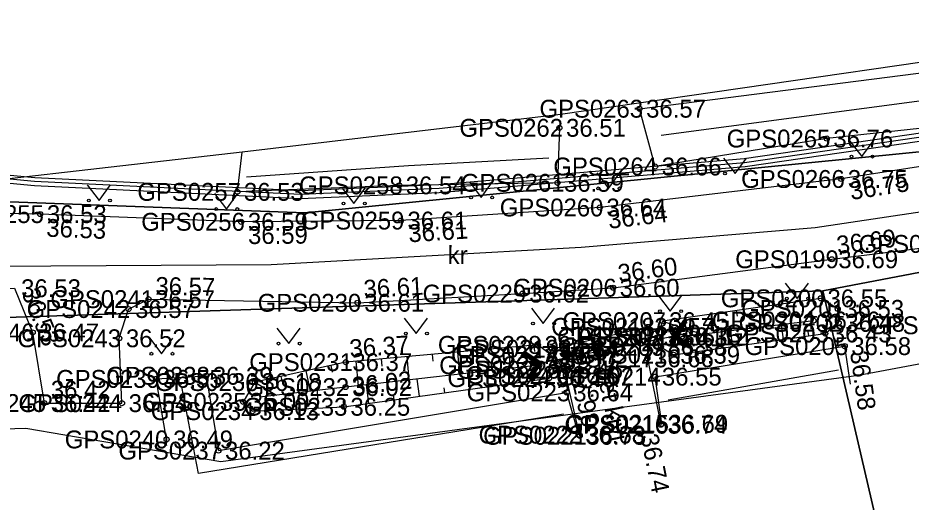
# Model space of a CAD drawing. Extents: x 626224 to 628280, y 6467750 to 6471135.
# Drawn here: x 627611.98 to 627646.98, y 6468609.95 to 6468628.94 of the extents above; entities that cross this region are included whole.
import ezdxf

# ---------------------------------------------------------------- set-up
doc = ezdxf.new("R2010")
doc.units = 0
for name, color, linetype in [('HALJASTUS', 7, 'Continuous'), ('KORGUS-EH2000', 7, 'Continuous'), ('KPKAABEL', 7, 'Continuous'), ('MOOTKORG-EH2000', 7, 'Continuous'), ('MOOTMPUNKT', 7, 'Continuous'), ('MOOTNR', 7, 'Continuous'), ('MOOTPIIR', 7, 'Continuous'), ('MPKAABEL', 7, 'Continuous'), ('PIIR', 7, 'Continuous'), ('RELJEEF', 7, 'Continuous'), ('TEE', 7, 'Continuous'), ('Tee Muu tee Kruuskate', 7, 'Continuous'), ('TRUUP', 7, 'Continuous')]:
    doc.layers.add(name, color=color, linetype=linetype)

msp = doc.modelspace()

# ---------------------------------------------------------------- linework, layer by layer
at = {"layer": 'HALJASTUS'}
for p, q in [((627637.187, 6468624.338), (627656.639, 6468626.929)), ((627644.579, 6468624.104), (627645.043, 6468623.497)), ((627645.043, 6468623.497), (627645.488, 6468624.104)), ((627639.623, 6468623.44), (627640.087, 6468622.834)), ((627640.087, 6468622.834), (627640.532, 6468623.44)), ((627634.659, 6468622.859), (627635.122, 6468622.252)), ((627635.122, 6468622.252), (627635.568, 6468622.859)), ((627629.672, 6468622.506), (627630.135, 6468621.899)), ((627630.135, 6468621.899), (627630.581, 6468622.506)), ((627614.695, 6468622.386), (627615.159, 6468621.779)), ((627615.159, 6468621.779), (627615.604, 6468622.386)), ((627624.678, 6468622.264), (627625.141, 6468621.658)), ((627625.141, 6468621.658), (627625.587, 6468622.264)), ((627619.684, 6468622.049), (627620.147, 6468621.442)), ((627620.147, 6468621.442), (627620.593, 6468622.049)), ((627642.05, 6468618.542), (627642.514, 6468617.935)), ((627642.514, 6468617.935), (627642.959, 6468618.542)), ((627637.075, 6468618.044), (627637.539, 6468617.437)), ((627637.539, 6468617.437), (627637.984, 6468618.044)), ((627632.099, 6468617.561), (627632.562, 6468616.955)), ((627632.562, 6468616.955), (627633.008, 6468617.561)), ((627627.114, 6468617.168), (627627.578, 6468616.561)), ((627627.578, 6468616.561), (627628.023, 6468617.168)), ((627622.13, 6468616.774), (627622.593, 6468616.167)), ((627622.593, 6468616.167), (627623.039, 6468616.774)), ((627617.145, 6468616.38), (627617.609, 6468615.773)), ((627617.609, 6468615.773), (627618.054, 6468616.38)), ((627637.463, 6468613.958), (627644.128, 6468615.143))]:
    msp.add_line(p, q, dxfattribs=at)
for points in [[(627636.336, 6468625.375), (627656.875, 6468628.003), (627657.149, 6468625.947), (627654.322, 6468625.361), (627643.674, 6468624.206), (627636.948, 6468623.11), (627636.336, 6468625.375)], [(627633.198, 6468624.626), (627633.117, 6468622.47), (627626.917, 6468622.371), (627620.576, 6468622.116), (627620.768, 6468623.676)], [(627620.933, 6468622.704), (627627.29, 6468623.144), (627632.786, 6468623.456)], [(627637.208, 6468613.025), (627636.953, 6468614.872), (627644.375, 6468616.069), (627644.586, 6468614.575)], [(627617.803, 6468612.411), (627617.396, 6468614.784), (627619.355, 6468614.906), (627619.834, 6468611.973), (627633.481, 6468614.256), (627633.95, 6468612.598)], [(627633.361, 6468613.408), (627619.06, 6468611.08), (627618.4, 6468614.472)]]:
    msp.add_lwpolyline(points, dxfattribs=at)
for centre in [(627644.641, 6468623.497), (627645.47, 6468623.497), (627639.686, 6468622.834), (627640.515, 6468622.834), (627634.721, 6468622.252), (627635.55, 6468622.252), (627614.757, 6468621.779), (627615.586, 6468621.779), (627629.734, 6468621.899), (627630.563, 6468621.899), (627619.746, 6468621.442), (627620.575, 6468621.442), (627624.74, 6468621.658), (627625.569, 6468621.658), (627642.113, 6468617.935), (627642.942, 6468617.935), (627637.138, 6468617.437), (627637.967, 6468617.437), (627632.161, 6468616.955), (627632.99, 6468616.955), (627627.177, 6468616.561), (627628.006, 6468616.561), (627622.192, 6468616.167), (627623.021, 6468616.167), (627617.208, 6468615.773), (627618.037, 6468615.773)]:
    msp.add_circle(centre, 0.055, dxfattribs=at)
at = {"layer": 'KORGUS-EH2000'}
for centre in [(627644.239, 6468622.621), (627634.78, 6468621.504), (627612.855, 6468621.244), (627626.983, 6468620.991), (627620.731, 6468620.942), (627643.867, 6468619.473), (627635.301, 6468618.359), (627617.098, 6468617.911), (627625.292, 6468617.768), (627643.159, 6468617.072), (627637.992, 6468616.444), (627644.375, 6468616.069), (627632.902, 6468615.968), (627624.824, 6468615.441), (627624.818, 6468614.464), (627613.007, 6468613.838), (627637.175, 6468612.988), (627633.992, 6468612.554), (627619.834, 6468611.973)]:
    msp.add_circle(centre, 0.1, dxfattribs=at)
at = {"layer": 'KPKAABEL'}
msp.add_lwpolyline([(627685.782, 6468640.643), (627682.599, 6468638.441), (627678.043, 6468635.809), (627672.046, 6468634.344), (627660.214, 6468631.662), (627657.997, 6468630.954), (627658.117, 6468626.708), (627657.689, 6468626.13), (627652.495, 6468625.008), (627640.455, 6468623.259), (627628.481, 6468622.246), (627623.048, 6468622.007), (627612.632, 6468622.516), (627609.034, 6468622.858), (627605.474, 6468623.034), (627601.854, 6468622.409), (627599.956, 6468622.4), (627599.775, 6468623.347)], dxfattribs=at)
at = {"layer": 'MOOTMPUNKT'}
for centre in [(627636.336, 6468625.375), (627633.198, 6468624.626), (627643.674, 6468624.206), (627636.948, 6468623.11), (627626.917, 6468622.371), (627633.117, 6468622.47), (627644.239, 6468622.621), (627620.576, 6468622.116), (627634.78, 6468621.504), (627612.855, 6468621.244), (627626.983, 6468620.991), (627620.731, 6468620.942), (627643.867, 6468619.473), (627635.301, 6468618.359), (627617.098, 6468617.911), (627631.755, 6468618.128), (627643.444, 6468617.942), (627616.311, 6468617.523), (627625.292, 6468617.768), (627644.103, 6468617.529), (627636.656, 6468616.822), (627637.236, 6468617.048), (627643.159, 6468617.072), (627644.14, 6468616.982), (627612.555, 6468616.606), (627637.028, 6468616.411), (627637.706, 6468616.448), (627637.721, 6468616.454), (627637.992, 6468616.444), (627643.614, 6468616.565), (627615.95, 6468616.377), (627632.355, 6468616.117), (627644.375, 6468616.069), (627632.875, 6468615.718), (627632.902, 6468615.968), (627637.175, 6468616.04), (627637.673, 6468615.732), (627624.824, 6468615.441), (627636.646, 6468615.589), (627632.407, 6468615.317), (627633.088, 6468615.145), (627617.396, 6468614.784), (627619.355, 6468614.906), (627621.265, 6468614.66), (627632.799, 6468614.816), (627633.451, 6468614.936), (627636.953, 6468614.872), (627624.818, 6468614.464), (627633.481, 6468614.256), (627613.007, 6468613.838), (627616.056, 6468613.833), (627620.799, 6468613.886), (627624.748, 6468613.691), (627621.174, 6468613.521), (627637.175, 6468612.988), (627637.208, 6468613.025), (627633.95, 6468612.598), (627633.992, 6468612.554), (627617.803, 6468612.411), (627619.834, 6468611.973)]:
    msp.add_circle(centre, 0.1, dxfattribs=at)
at = {"layer": 'MOOTPIIR'}
msp.add_lwpolyline([(627656.533, 6468628.521), (627633.238, 6468625.152), (627620.768, 6468623.676), (627605.69, 6468621.95), (627605.321, 6468621.364), (627605.451, 6468618.323), (627604.849, 6468612.629), (627612.287, 6468612.849), (627619.934, 6468611.546), (627644.92, 6468614.927), (627687.389, 6468622.904)], dxfattribs=at)
at = {"layer": 'MPKAABEL'}
for points in [[(627685.699, 6468640.768), (627682.519, 6468638.568), (627677.987, 6468635.95), (627672.012, 6468634.49), (627660.175, 6468631.807), (627657.844, 6468631.063), (627657.966, 6468626.756), (627657.602, 6468626.265), (627652.468, 6468625.156), (627640.438, 6468623.408), (627628.471, 6468622.396), (627623.048, 6468622.157), (627612.643, 6468622.666), (627609.045, 6468623.008), (627605.465, 6468623.185), (627601.841, 6468622.559), (627601.344, 6468627.176), (627599.992, 6468627.142), (627599.551, 6468626.364)], [(627599.73, 6468626.375), (627600.081, 6468626.994), (627601.209, 6468627.023), (627601.759, 6468622.259), (627605.483, 6468622.883), (627609.023, 6468622.708), (627612.621, 6468622.366), (627623.048, 6468621.857), (627628.491, 6468622.096), (627640.472, 6468623.11), (627652.522, 6468624.86), (627657.776, 6468625.995), (627658.268, 6468626.66), (627658.15, 6468630.845), (627660.253, 6468631.517), (627672.08, 6468634.198), (627673.058, 6468632.736)]]:
    msp.add_lwpolyline(points, dxfattribs=at)
at = {"layer": 'PIIR'}
for points in [[(627654.85, 6468663.52), (627663.66, 6468662.2), (627686.69, 6468632.75), (627684.35, 6468632.16), (627652.69, 6468624.22), (627623.24, 6468621.3), (627605.69, 6468621.95), (627588.94, 6468620.18), (627586.23, 6468625.97), (627596.31, 6468635.4), (627619.6, 6468659.76), (627624.98, 6468665.39), (627633.24, 6468674.95), (627637.73, 6468680.5), (627640.48, 6468683.65), (627644.86, 6468680.34)], [(627746.91, 6468541.23), (627666.94, 6468517.08), (627653, 6468577.43), (627643.52, 6468618.24), (627688.18, 6468626.77)], [(627599.49, 6468616.8), (627643.52, 6468618.24), (627653, 6468577.43), (627666.94, 6468517.08), (627608.44, 6468499.25), (627602.15, 6468514.88), (627588.44, 6468509.87), (627563.73, 6468583.75), (627555.29, 6468612.05)]]:
    msp.add_lwpolyline(points, close=True, dxfattribs=at)
msp.add_lwpolyline([(627401.5, 6468603.97), (627489.68, 6468613.41), (627577.55, 6468622.81), (627581.38, 6468622.85), (627583, 6468623.57), (627584.27, 6468624.13), (627586.23, 6468625.97), (627588.94, 6468620.18), (627605.69, 6468621.95), (627623.24, 6468621.3), (627652.69, 6468624.22), (627684.35, 6468632.16), (627688.18, 6468626.77), (627643.52, 6468618.24), (627599.49, 6468616.8), (627555.29, 6468612.05), (627411.34, 6468595.13)], dxfattribs=at)
at = {"layer": 'RELJEEF'}
for p, q in [((627641.12, 6468617.607), (627641.23, 6468616.838)), ((627642.109, 6468617.75), (627642.143, 6468617.512)), ((627639.14, 6468617.322), (627639.244, 6468616.596)), ((627640.13, 6468617.465), (627640.162, 6468617.24)), ((627637.236, 6468617.048), (627638.787, 6468616.541)), ((627638.15, 6468617.18), (627638.181, 6468616.969)), ((627641.976, 6468616.335), (627641.894, 6468616.919)), ((627639.995, 6468616.058), (627639.908, 6468616.677)), ((627642.966, 6468616.474), (627642.942, 6468616.644)), ((627637.149, 6468616.105), (627637.407, 6468616.207)), ((627640.985, 6468616.196), (627640.96, 6468616.377)), ((627629.206, 6468615.834), (627629.284, 6468614.966)), ((627630.202, 6468615.924), (627630.225, 6468615.67)), ((627631.198, 6468616.013), (627631.272, 6468615.189)), ((627632.194, 6468616.102), (627632.215, 6468615.862)), ((627639.005, 6468615.919), (627638.978, 6468616.11)), ((627625.222, 6468615.477), (627625.308, 6468614.519)), ((627626.218, 6468615.566), (627626.243, 6468615.286)), ((627627.214, 6468615.656), (627627.296, 6468614.742)), ((627628.21, 6468615.745), (627628.234, 6468615.478)), ((627632.939, 6468615.547), (627632.282, 6468615.303)), ((627624.237, 6468615.313), (627624.296, 6468615.045)), ((627631.676, 6468614.659), (627631.597, 6468615.226)), ((627622.284, 6468614.884), (627622.33, 6468614.675)), ((627623.261, 6468615.098), (627623.435, 6468614.303)), ((627627.714, 6468614.105), (627627.62, 6468614.779)), ((627629.695, 6468614.382), (627629.609, 6468615.002)), ((627621.265, 6468614.66), (627622.115, 6468614.149)), ((627625.734, 6468613.829), (627625.632, 6468614.555)), ((627628.705, 6468614.244), (627628.678, 6468614.438)), ((627630.686, 6468614.52), (627630.661, 6468614.699)), ((627621.747, 6468613.548), (627621.72, 6468614.103)), ((627623.744, 6468613.643), (627623.712, 6468614.335)), ((627626.724, 6468613.967), (627626.695, 6468614.177)), ((627622.746, 6468613.596), (627622.737, 6468613.783)), ((627624.743, 6468613.691), (627624.732, 6468613.919))]:
    msp.add_line(p, q, dxfattribs=at)
for points in [[(627637.236, 6468617.048), (627637.028, 6468616.411), (627637.175, 6468616.04), (627637.673, 6468615.732), (627643.614, 6468616.565), (627644.14, 6468616.982), (627644.103, 6468617.529), (627643.444, 6468617.942), (627637.236, 6468617.048)], [(627637.992, 6468616.444), (627643.159, 6468617.072)], [(627621.265, 6468614.66), (627620.799, 6468613.886), (627621.174, 6468613.521), (627624.748, 6468613.691), (627632.799, 6468614.816), (627633.088, 6468615.145), (627632.875, 6468615.718), (627632.355, 6468616.117), (627624.824, 6468615.441), (627621.265, 6468614.66)], [(627632.407, 6468615.317), (627624.818, 6468614.464), (627621.442, 6468614.071)]]:
    msp.add_lwpolyline(points, dxfattribs=at)
at = {"layer": 'TEE'}
for points in [[(627655.323, 6468624.553), (627654.099, 6468624.153), (627644.239, 6468622.621), (627634.78, 6468621.504), (627626.983, 6468620.991), (627620.731, 6468620.942), (627612.855, 6468621.244), (627605.321, 6468621.364)], [(627605.451, 6468618.323), (627611.844, 6468618.339), (627612.555, 6468616.606), (627613.007, 6468613.838), (627616.056, 6468613.833), (627615.95, 6468616.377), (627616.311, 6468617.523), (627617.098, 6468617.911), (627625.292, 6468617.768), (627631.755, 6468618.128), (627635.301, 6468618.359), (627643.867, 6468619.473), (627648.701, 6468620.075), (627654.943, 6468621.043), (627656.855, 6468621.064)], [(627633.992, 6468612.554), (627633.451, 6468614.936), (627632.902, 6468615.968), (627636.656, 6468616.822), (627636.646, 6468615.589), (627637.175, 6468612.988)]]:
    msp.add_lwpolyline(points, dxfattribs=at)
at = {"layer": 'Tee Muu tee Kruuskate'}
msp.add_lwpolyline([(627655.281, 6468622.513), (627643.219, 6468620.707), (627634.046, 6468619.94), (627621.905, 6468619.252), (627606.783, 6468619.17), (627583.198, 6468617.485), (627569.985, 6468616.221), (627554.678, 6468614.391), (627502.881, 6468608.768), (627472.157, 6468604.735), (627458.252, 6468603.133), (627409.627, 6468597.894), (627406.06, 6468597.51)], dxfattribs=at)
at = {"layer": 'TRUUP'}
for p, q in [((627638.054, 6468617.082), (627637.622, 6468616.435)), ((627638.113, 6468617.043), (627637.721, 6468616.454)), ((627638.081, 6468616.866), (627637.806, 6468616.71)), ((627638.172, 6468617.003), (627637.82, 6468616.474)), ((627638.112, 6468616.913), (627637.837, 6468616.756)), ((627638.143, 6468616.959), (627637.868, 6468616.803)), ((627638.171, 6468617.004), (627637.898, 6468616.849)), ((627638.148, 6468617.019), (627637.929, 6468616.895)), ((627638.125, 6468617.035), (627637.96, 6468616.941)), ((627638.102, 6468617.05), (627637.991, 6468616.988)), ((627638.078, 6468617.066), (627638.022, 6468617.034)), ((627638.172, 6468617.003), (627638.054, 6468617.082)), ((627637.896, 6468616.589), (627637.623, 6468616.434)), ((627637.865, 6468616.543), (627637.647, 6468616.418)), ((627637.927, 6468616.635), (627637.652, 6468616.479)), ((627637.958, 6468616.681), (627637.683, 6468616.525)), ((627637.989, 6468616.728), (627637.713, 6468616.571)), ((627638.019, 6468616.774), (627637.744, 6468616.618)), ((627638.05, 6468616.82), (627637.775, 6468616.664)), ((627637.721, 6468616.454), (627632.404, 6468615.39)), ((627637.622, 6468616.435), (627638.27, 6468616.003)), ((627637.835, 6468616.496), (627637.67, 6468616.403)), ((627637.832, 6468616.466), (627637.693, 6468616.387)), ((627637.855, 6468616.451), (627637.716, 6468616.372)), ((627637.721, 6468616.454), (627638.309, 6468616.062)), ((627637.878, 6468616.435), (627637.74, 6468616.356)), ((627637.902, 6468616.42), (627637.763, 6468616.341)), ((627637.925, 6468616.404), (627637.786, 6468616.325)), ((627637.948, 6468616.389), (627637.81, 6468616.31)), ((627637.82, 6468616.474), (627638.349, 6468616.122)), ((627637.972, 6468616.373), (627637.833, 6468616.294)), ((627637.995, 6468616.357), (627637.856, 6468616.279)), ((627638.018, 6468616.342), (627637.879, 6468616.263)), ((627638.041, 6468616.326), (627637.903, 6468616.248)), ((627638.065, 6468616.311), (627637.926, 6468616.232)), ((627638.088, 6468616.295), (627637.949, 6468616.217)), ((627638.111, 6468616.28), (627637.973, 6468616.201)), ((627638.135, 6468616.264), (627637.996, 6468616.186)), ((627638.158, 6468616.249), (627638.019, 6468616.17)), ((627638.181, 6468616.233), (627638.043, 6468616.155)), ((627638.205, 6468616.218), (627638.066, 6468616.139)), ((627638.228, 6468616.202), (627638.089, 6468616.124)), ((627638.251, 6468616.187), (627638.112, 6468616.108)), ((627638.274, 6468616.171), (627638.136, 6468616.092)), ((627638.298, 6468616.156), (627638.159, 6468616.077)), ((627631.776, 6468615.723), (627631.855, 6468615.841)), ((627631.801, 6468615.76), (627631.896, 6468615.814)), ((627631.832, 6468615.806), (627631.873, 6468615.829)), ((627632.503, 6468615.41), (627631.855, 6468615.841)), ((627638.321, 6468616.14), (627638.182, 6468616.061)), ((627638.344, 6468616.125), (627638.206, 6468616.046)), ((627638.324, 6468616.084), (627638.229, 6468616.03)), ((627638.293, 6468616.038), (627638.252, 6468616.015)), ((627638.349, 6468616.122), (627638.27, 6468616.003)), ((627632.306, 6468615.37), (627631.776, 6468615.723)), ((627631.781, 6468615.72), (627631.92, 6468615.798)), ((627631.804, 6468615.704), (627631.943, 6468615.783)), ((627632.404, 6468615.39), (627631.816, 6468615.782)), ((627631.828, 6468615.689), (627631.966, 6468615.767)), ((627631.851, 6468615.673), (627631.99, 6468615.752)), ((627631.874, 6468615.658), (627632.013, 6468615.736)), ((627631.897, 6468615.642), (627632.036, 6468615.721)), ((627631.921, 6468615.626), (627632.059, 6468615.705)), ((627631.944, 6468615.611), (627632.083, 6468615.69)), ((627631.967, 6468615.595), (627632.106, 6468615.674)), ((627631.991, 6468615.58), (627632.129, 6468615.659)), ((627632.014, 6468615.564), (627632.153, 6468615.643)), ((627632.037, 6468615.549), (627632.176, 6468615.628)), ((627632.061, 6468615.533), (627632.199, 6468615.612)), ((627632.084, 6468615.518), (627632.222, 6468615.596)), ((627632.107, 6468615.502), (627632.246, 6468615.581)), ((627632.13, 6468615.487), (627632.269, 6468615.565)), ((627632.154, 6468615.471), (627632.292, 6468615.55)), ((627632.177, 6468615.456), (627632.316, 6468615.534)), ((627632.2, 6468615.44), (627632.339, 6468615.519)), ((627632.224, 6468615.425), (627632.362, 6468615.503)), ((627632.247, 6468615.409), (627632.386, 6468615.488)), ((627632.27, 6468615.394), (627632.409, 6468615.472)), ((627632.294, 6468615.378), (627632.432, 6468615.457)), ((627631.953, 6468614.841), (627632.306, 6468615.37)), ((627632.012, 6468614.801), (627632.404, 6468615.39)), ((627632.044, 6468614.978), (627632.319, 6468615.134)), ((627632.071, 6468614.762), (627632.503, 6468615.41)), ((627632.075, 6468615.024), (627632.35, 6468615.18)), ((627632.106, 6468615.07), (627632.381, 6468615.227)), ((627632.137, 6468615.117), (627632.412, 6468615.273)), ((627632.167, 6468615.163), (627632.443, 6468615.319)), ((627632.198, 6468615.209), (627632.473, 6468615.365)), ((627632.229, 6468615.255), (627632.502, 6468615.41)), ((627632.26, 6468615.302), (627632.479, 6468615.426)), ((627632.291, 6468615.348), (627632.455, 6468615.441)), ((627631.953, 6468614.841), (627632.071, 6468614.762)), ((627631.954, 6468614.84), (627632.227, 6468614.995)), ((627631.977, 6468614.825), (627632.196, 6468614.949)), ((627631.983, 6468614.885), (627632.258, 6468615.042)), ((627632, 6468614.809), (627632.165, 6468614.903)), ((627632.013, 6468614.932), (627632.289, 6468615.088)), ((627632.024, 6468614.794), (627632.135, 6468614.857)), ((627632.047, 6468614.778), (627632.104, 6468614.81))]:
    msp.add_line(p, q, dxfattribs=at)

# ---------------------------------------------------------------- texts
at = {"layer": 'KORGUS-EH2000'}
for s, rotation, p in [(' 36.75', 8.8335, (627644.374, 6468621.756)), (' 36.64', 6.7343, (627634.883, 6468620.635)), (' 36.53', 357.7997, (627612.822, 6468620.37)), (' 36.59', 0.4564, (627620.738, 6468620.067)), (' 36.61', 3.7574, (627627.04, 6468620.118)), (' 36.69', 7.0969, (627643.845, 6468619.647)), (' 36.60', 7.4084, (627635.278, 6468618.533)), (' 36.57', 359.0044, (627617.101, 6468618.085)), (' 36.61', 3.1837, (627625.282, 6468617.943)), (' 36.53', 292.3114, (627612.006, 6468618.405)), (' 36.37', 4.1965, (627624.737, 6468615.605)), (' 36.64', 12.826, (627633.096, 6468615.115)), (' 36.58', 278.0437, (627644.548, 6468616.093)), (' 36.73', 102.7877, (627634.845, 6468612.747)), (' 36.02', 6.4145, (627624.857, 6468614.116)), (' 36.42', 359.9079, (627613.008, 6468614.013)), (' 36.74', 281.4949, (627636.317, 6468612.813))]:
    msp.add_text(s, height=0.7, rotation=rotation, dxfattribs=at).set_placement(p)
for s, p in [(' 36.26', (627643.159, 6468616.723)), (' 36.12', (627637.992, 6468616.094)), (' 36.22', (627619.834, 6468611.623))]:
    msp.add_text(s, height=0.7, dxfattribs=at).set_placement(p)
at = {"layer": 'MOOTKORG-EH2000'}
for s, p in [(' 36.57', (627636.336, 6468625.025)), (' 36.51', (627633.198, 6468624.276)), (' 36.76', (627643.674, 6468623.856)), (' 36.66', (627636.948, 6468622.76)), (' 36.59', (627633.117, 6468622.12)), (' 36.75', (627644.239, 6468622.271)), (' 36.53', (627620.576, 6468621.766)), (' 36.54', (627626.917, 6468622.021)), (' 36.64', (627634.78, 6468621.154)), (' 36.53', (627612.855, 6468620.894)), (' 36.59', (627620.731, 6468620.592)), (' 36.61', (627626.983, 6468620.641)), (' 36.69', (627643.867, 6468619.123)), (' 36.53', (627611.844, 6468617.989)), (' 36.60', (627635.301, 6468618.009)), (' 36.57', (627617.098, 6468617.561)), (' 36.62', (627631.755, 6468617.778)), (' 36.55', (627643.444, 6468617.592)), (' 36.61', (627625.292, 6468617.418)), (' 36.57', (627616.311, 6468617.173)), (' 36.53', (627644.103, 6468617.179)), (' 36.45', (627637.236, 6468616.698)), (' 36.26', (627643.159, 6468616.723)), (' 36.48', (627644.14, 6468616.632)), (' 36.47', (627612.555, 6468616.256)), (' 36.57', (627636.656, 6468616.472)), (' 36.43', (627643.614, 6468616.215)), (' 36.52', (627615.95, 6468616.026)), (' 36.41', (627637.028, 6468616.061)), (' 36.35', (627637.706, 6468616.098)), (' 36.15', (627637.721, 6468616.104)), (' 36.12', (627637.992, 6468616.094)), (' 36.54', (627632.355, 6468615.767)), (' 36.64', (627632.902, 6468615.618)), (' 36.38', (627637.175, 6468615.69)), (' 36.58', (627644.375, 6468615.719)), (' 36.47', (627632.875, 6468615.368)), (' 36.66', (627636.646, 6468615.239)), (' 36.39', (627637.673, 6468615.382)), (' 36.37', (627624.824, 6468615.092)), (' 36.21', (627632.407, 6468614.967)), (' 36.46', (627633.088, 6468614.795)), (' 36.55', (627617.396, 6468614.434)), (' 36.39', (627619.355, 6468614.556)), (' 36.45', (627632.799, 6468614.466)), (' 36.67', (627633.451, 6468614.586)), (' 36.55', (627636.953, 6468614.522)), (' 36.18', (627621.265, 6468614.31)), (' 36.02', (627624.818, 6468614.114)), (' 36.64', (627633.481, 6468613.906)), (' 36.42', (627613.007, 6468613.488)), (' 36.54', (627616.056, 6468613.483)), (' 36.09', (627620.799, 6468613.536)), (' 36.13', (627621.174, 6468613.171)), (' 36.25', (627624.748, 6468613.341)), (' 36.69', (627637.208, 6468612.675)), (' 36.74', (627637.175, 6468612.638)), (' 36.49', (627617.803, 6468612.061)), (' 36.68', (627633.95, 6468612.248)), (' 36.73', (627633.992, 6468612.204)), (' 36.22', (627619.834, 6468611.623))]:
    msp.add_text(s, height=0.7, dxfattribs=at).set_placement(p)
at = {"layer": 'MOOTNR'}
for s, p in [('GPS0263 ', (627632.416, 6468625.025)), ('GPS0262 ', (627629.279, 6468624.276)), ('GPS0265 ', (627639.754, 6468623.856)), ('GPS0264 ', (627632.959, 6468622.76)), ('GPS0261 ', (627629.338, 6468622.12)), ('GPS0266 ', (627640.319, 6468622.271)), ('GPS0257 ', (627616.657, 6468621.766)), ('GPS0258 ', (627622.997, 6468622.021)), ('GPS0260 ', (627630.861, 6468621.154)), ('GPS0255 ', (627608.935, 6468620.894)), ('GPS0256 ', (627616.811, 6468620.592)), ('GPS0259 ', (627623.063, 6468620.641)), ('GPS0196 ', (627644.921, 6468619.725)), ('GPS0199 ', (627640.087, 6468619.123)), ('GPS0206 ', (627631.381, 6468618.009)), ('GPS0241 ', (627613.248, 6468617.561)), ('GPS0229 ', (627627.835, 6468617.778)), ('GPS0200 ', (627639.524, 6468617.592)), ('GPS0230 ', (627621.372, 6468617.418)), ('GPS0242 ', (627612.321, 6468617.173)), ('GPS0201 ', (627640.323, 6468617.179)), ('GPS0207 ', (627633.316, 6468616.698)), ('GPS0204 ', (627639.169, 6468616.723)), ('GPS0202 ', (627640.22, 6468616.632)), ('GPS0198 ', (627645.297, 6468616.536)), ('GPS0246 ', (627608.566, 6468616.256)), ('GPS0218 ', (627632.877, 6468616.472)), ('GPS0203 ', (627639.694, 6468616.215)), ('GPS0243 ', (627611.96, 6468616.026)), ('GPS0208 ', (627633.108, 6468616.061)), ('GPS0213 ', (627633.926, 6468616.098)), ('GPS0212 ', (627633.941, 6468616.104)), ('GPS0211 ', (627634.352, 6468616.094)), ('GPS0228 ', (627628.435, 6468615.767)), ('GPS0219 ', (627629.122, 6468615.618)), ('GPS0209 ', (627633.255, 6468615.69)), ('GPS0205 ', (627640.455, 6468615.719)), ('GPS0227 ', (627628.955, 6468615.368)), ('GPS0217 ', (627632.866, 6468615.239)), ('GPS0210 ', (627633.893, 6468615.382)), ('GPS0231 ', (627621.044, 6468615.092)), ('GPS0225 ', (627628.488, 6468614.967)), ('GPS0226 ', (627629.168, 6468614.795)), ('GPS0239 ', (627613.476, 6468614.434)), ('GPS0238 ', (627615.436, 6468614.556)), ('GPS0224 ', (627628.809, 6468614.466)), ('GPS0220 ', (627629.531, 6468614.586)), ('GPS0214 ', (627633.103, 6468614.522)), ('GPS0236 ', (627617.345, 6468614.31)), ('GPS0232 ', (627620.899, 6468614.114)), ('GPS0223 ', (627629.562, 6468613.906)), ('GPS0245 ', (627609.018, 6468613.488)), ('GPS0244 ', (627611.997, 6468613.483)), ('GPS0235 ', (627616.879, 6468613.536)), ('GPS0234 ', (627617.184, 6468613.171)), ('GPS0233 ', (627620.828, 6468613.341)), ('GPS0215 ', (627633.429, 6468612.675)), ('GPS0216 ', (627633.395, 6468612.638)), ('GPS0240 ', (627613.814, 6468612.061)), ('GPS0222 ', (627630.03, 6468612.248)), ('GPS0221 ', (627630.212, 6468612.204)), ('GPS0237 ', (627615.915, 6468611.623))]:
    msp.add_text(s, height=0.7, dxfattribs=at).set_placement(p)
at = {"layer": 'TEE'}
for s, rotation, p in [('kr', 359.54, (627628.818, 6468619.294)), ('bet kivi', 281.7481, (627634.642, 6468615.16))]:
    msp.add_text(s, height=0.7, rotation=rotation, dxfattribs=at).set_placement(p)

doc.saveas('drawing.dxf')
